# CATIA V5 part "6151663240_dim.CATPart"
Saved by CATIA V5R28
Part number: 6151663240_dim
Source: made
Property "PROI_CREATED_ON": "12/17/2008 9:21:37 AM"
Property "BLANK_DRAWING": "--"
Property "DRAWN_BY": "FPA"
Property "FINISH": "--"
Property "HEAT_TREATMENT": "ASSIGN"
Property "MATERIAL": "ASSIGN"
Property "PROJECT": "--"
Property "PROTOTYPE_NO": "BE65177"
Property "RELATED_DRAWING": "--"
Property "COMPLETE_MATERIAL": "ASSIGN-ASSIGN"
Property "DESCRIPTION": "EABCLRT110-1300"
Property "DRAWING_EXIST": "--"
Property "MANUFACTURER": "--"
Property "MANUFACTURER_2": "--"
Property "MANUFACTURER_REF": "--"
Property "TYPE_PART": "A"
Property "TODAY_DATE": "2024/08/13"
Property "PDMREV": "01.2"
Property "PDMRL": "Production"
Property "PROI_REVISION": "01"
Property "PROI_VERSION": "2"
Property "PROI_RELEASE": "Production"
Property "PTC_MODIFIED": false
Property "MFG_WP_MATERIAL": "ASSIGN"
Property "COMPANY_CODE": "---"
Property "DESCRIPTION_JP": "--"
Property "PQP_DOCUMENT": "--"
Property "SUPPLIER": "--"
Property "REFERENCE": "6151663240"
Property "PTC_WM_REVISION": "01"
Property "PTC_WM_ITERATION": "2"
Property "PTC_WM_VERSION": "01.2"
Property "PTC_WM_LIFECYCLE_STATE": "Production"
Property "PTC_WM_LIFECYCLE": "Design_Process"
Property "PTC_WM_LOCATION": "/Products/BATTERY TOOLS/A3320 - EABLRT/9-01-Dimensional Drawings and 3D"
Property "PTC_WM_CREATED_BY": "Florian Pavageau (Grefpav) (Grefpav: CPD)"
Property "PTC_WM_CREATED_ON": "20-Mar-25 03:04:17 PM"
Property "PTC_WM_MODIFIED_BY": "Administrateur Organisation CPD (INTRALINK: CPD)"
Property "PTC_WM_MODIFIED_ON": "10-Feb-26 12:18:12 PM"
Property "PTC_WM_TEAM": "Default"
Property "PTC_ORGANIZATION_ID": "CPD"
Property "PTC_WM_NAME": "6151663240_dim.prt"
Property "PTC_WM_NUMBER": "6151663240_DIM.PRT"
Property "PTC_COMMON_NAME": "6151663240_dim.prt"
Property "PTC_MASTER_MATERIAL": "ASSIGN"
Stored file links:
  d:\ptc\Echange\temp\6151663240_dim.CATPart

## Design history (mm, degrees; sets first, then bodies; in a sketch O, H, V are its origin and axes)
AxisSystem1 "CS0": origin (0, 0, 0), X (1, 0, 0), Y (0, 1, 0), Z (0, 0, 1)
Set1
  DatumSurface1 "Sheet.1"
  DatumSurface2 "Sheet.2"
  DatumSurface3 "Sheet.3"
  DatumSurface4 "Sheet.4"
  DatumSurface5 "Sheet.5"
  DatumSurface6 "Sheet.6"
  DatumSurface7 "Sheet.7"
  DatumSurface8 "Sheet.8"
  DatumSurface9 "Sheet.9"
  DatumSurface10 "Sheet.10"
  DatumSurface11 "Sheet.11"
  DatumSurface12 "Sheet.12"
  DatumSurface13 "Sheet.13"
  DatumSurface14 "Sheet.14"
  DatumSurface15 "Sheet.15"
  DatumSurface16 "Sheet.16"
  DatumSurface17 "Sheet.17"
  DatumSurface18 "Sheet.18"
  DatumSurface19 "Sheet.19"
  DatumSurface20 "Sheet.20"
  DatumSurface21 "Sheet.21"
  DatumSurface22 "Sheet.22"
  DatumSurface23 "Sheet.23"
  DatumSurface24 "Sheet.24"
  DatumSurface25 "Sheet.25"
  Plane1 "RIGHT": stored without definition
  Plane2 "TOP": stored without definition
  Plane3 "FRONT": stored without definition
Body1 "PartBody" (main body)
